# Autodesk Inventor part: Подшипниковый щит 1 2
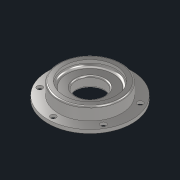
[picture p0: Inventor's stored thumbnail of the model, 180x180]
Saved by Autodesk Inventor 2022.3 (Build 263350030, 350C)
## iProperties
Created: 2022-08
Part Number: Подшипниковый щит 1 2
Material: Сталь 40ХНМА
Document SubType Name: Modeling
Designer: Карташов
Density: 7.85 g/cm^3
Appearance: С умеренной полировкой
Author: Карташов
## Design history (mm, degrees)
sketch "Эскиз1"
  geometry: L1 (0, 0)-(0, 34.001); L2 (22, 0)-(60, 0); L3 (60, 0)-(60, 5); L4 (60, 5)-(45, 5); L5 (45, 5)-(45, 21); L6 (43, 23)-(37, 23); L7 (37, 23)-(37, 18.76); L8 (33, 14.76)-(22, 14.76); L9 (20, 12.76)-(20, 2); A1 r 4 centre (33, 18.76) between (33, 14.76) and (37, 18.76); A2 r 2 centre (22, 12.76) between (22, 14.76) and (20, 12.76); A3 r 2 centre (22, 2) between (20, 2) and (22, 0); A4 r 2 centre (43, 21) between (45, 21) and (43, 23); 2 further points
  constraints: 18 end point, 8 point on circle, 8 tangent, 4 centre point, 4 horizontal, 4 vertical, 2 equal radius, 2 point on line, 1 horizontal alignment, 1 midpoint, 1 perpendicular
  dimensions: "d0" = 90 diameter of L5 point (0, 17); "d1" = 120 diameter of L3 L1; "d2" = 40 diameter of L9 L1; "d3" = 23 vertical distance of L2.end point (45, 23); "d4" = 5 distance of L2.end L3.end; "d5" = 8.24 distance between parallel lines of L8 L6; "d6" = 8 distance of point (45, 23) L6.end; "d7" = 4 radius of A1; "d8" = 2 radius of A2
revolve "Вращение1" sketch "Эскиз1" stored, may be unused: angle "d9" = 90 deg
sketch "Эскиз2"
  geometry: C1 r 45 at (0, 0) reference; C2 r 60 at (0, 0) reference; 2 further points
  constraints: 1 vertical alignment
  dimensions: "d10" = 52.5 distance of point (0, 0) point (0, -52.5)
  node "Спроецированная петля1"
sketch "Эскиз3"
  geometry: 2 further points
hole "Отверстие1" sketch "Эскиз3" at (0, 52.5) diameter "d11" = 8; stored, may be unused: countersink angle "d15" = 90 deg, drill point angle "d17" = 0 deg; dims "d12" = 6, "d13" = 13, "d14" = 1, "d16" = 22.5
pattern_circular "Круговой массив1" dims angle "d19" = 360 deg
node "Твердое тело1"
